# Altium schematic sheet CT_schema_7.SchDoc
size 251 x 159 mm
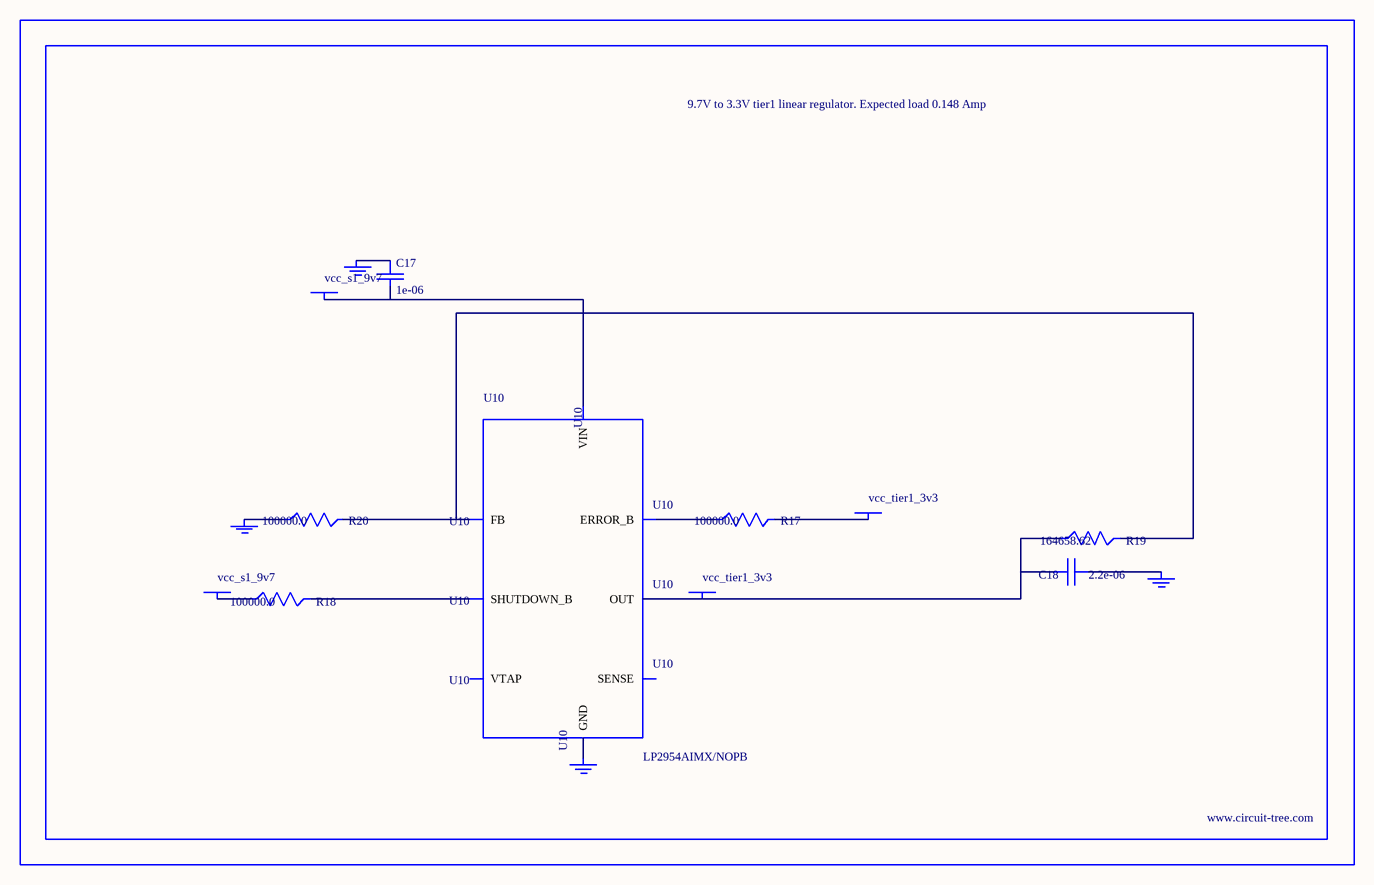
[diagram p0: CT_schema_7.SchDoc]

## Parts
BORDER6  (no value)
C17  1e-06  [EXV-9B]
C18  2.2e-06  [EXV-9B]
GND_INSTANCE_6_0  (no value)
GND_INSTANCE_6_1  (no value)
GND_INSTANCE_6_2  (no value)
GND_INSTANCE_6_3  (no value)
POWER_INSTANCE_6_0  vcc_s1_9v7
POWER_INSTANCE_6_1  vcc_tier1_3v3
POWER_INSTANCE_6_2  vcc_s1_9v7
POWER_INSTANCE_6_3  vcc_tier1_3v3
R17  100000.0  [R0603]
R18  100000.0  [R0603]
R19  164658.62  [R0603]
R20  100000.0  [R0603]
U10  LP2954AIMX/NOPB  [LP2954]

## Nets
NetC17_1: C17.1 GND_INSTANCE_6_2.0(GND)
NetC17_2: C17.2 POWER_INSTANCE_6_2.0(PWR) U10.8(VIN)
NetC18_1: C18.1 GND_INSTANCE_6_0.0(GND)
NetC18_2: C18.2 POWER_INSTANCE_6_3.0(PWR) R19.1 U10.1(OUT)
NetGND_INSTANCE_6_1_0: GND_INSTANCE_6_1.0(GND) R20.1
NetGND_INSTANCE_6_3_0: GND_INSTANCE_6_3.0(GND) U10.4(GND)
NetPOWER_INSTANCE_6_0_0: POWER_INSTANCE_6_0.0(PWR) R18.1
NetPOWER_INSTANCE_6_1_0: POWER_INSTANCE_6_1.0(PWR) R17.2
NetR17_1: R17.1 U10.5(ERROR_B)
NetR18_2: R18.2 U10.3(SHUTDOWN_B)
NetR19_2: R19.2 R20.2 U10.7(FB)

Not connected (* = marked no-connect by the designer): U10 2(SENSE) 6(VTAP)

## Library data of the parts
BORDER6 = BORDER_PAGE6
C17 = EDK105M050A9BAA
C18 = EDK225M050A9BAA
GND_INSTANCE_6_0-GND_INSTANCE_6_3 = GND
POWER_INSTANCE_6_0-POWER_INSTANCE_6_3 = PWR
R17 R18 R20 = RC0603JR-07100KL
R19 = R19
